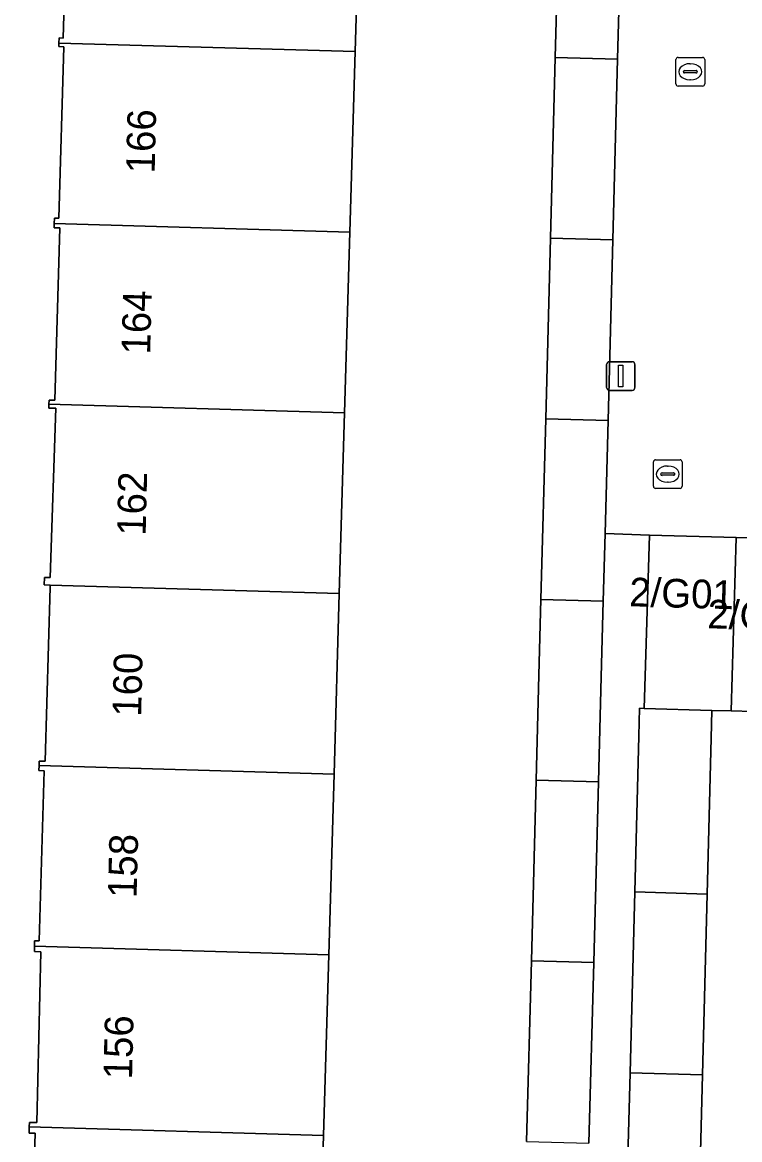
# Model space of a CAD drawing. Extents: x 162082 to 163401, y 388089 to 388636.
# Drawn here: x 162344.45 to 162369.45, y 388400.98 to 388439.93 of the extents above; entities that cross this region are included whole.
import ezdxf

# ---------------------------------------------------------------- set-up
doc = ezdxf.new("R2010")
doc.units = 0
for name, color, linetype in [('IMGEO_Erf', 7, 'Continuous'), ('IMGEO_Kolk', 7, 'Continuous'), ('IMGEO_Lichtmast', 7, 'Continuous'), ('IMGEO_Pand', 7, 'Continuous'), ('IMGEO_Pand_nummerreeks', 7, 'Continuous'), ('IMGEO_Rijbaan_lokaal_open', 7, 'Continuous'), ('IMGEO_Rioolput', 7, 'Continuous'), ('IMGEO_Voetpad_open', 7, 'Continuous')]:
    doc.layers.add(name, color=color, linetype=linetype)

msp = doc.modelspace()

# ---------------------------------------------------------------- linework, layer by layer
at = {"layer": 'IMGEO_Erf'}
for points in [[(162362.018, 388400.921), (162362.185, 388407.22), (162362.352, 388413.517), (162362.449, 388417.176), (162362.519, 388419.817), (162362.686, 388426.113), (162362.853, 388432.41), (162363.02, 388438.709), (162363.187, 388445.007), (162363.338, 388450.704), (162365.51, 388450.646), (162365.74, 388455.41), (162360.743, 388455.573), (162356.57, 388455.71), (162356.269, 388446.627), (162356.228, 388445.209), (162356.044, 388438.912), (162355.86, 388432.614), (162355.677, 388426.317), (162355.493, 388420.021), (162355.31, 388413.722), (162355.126, 388407.425), (162354.942, 388401.127), (162354.759, 388394.83)], [(162344.724, 388395.302), (162344.896, 388401.204), (162344.683, 388401.21), (162344.689, 388401.425), (162344.694, 388401.584), (162344.952, 388401.578), (162345.087, 388407.535), (162344.864, 388407.54), (162344.869, 388407.723), (162344.875, 388407.916), (162345.036, 388407.912), (162345.209, 388413.842), (162345.026, 388413.848), (162345.031, 388414.021), (162345.035, 388414.18), (162345.236, 388414.174), (162345.413, 388420.245), (162345.415, 388420.314), (162345.205, 388420.32), (162345.213, 388420.583), (162345.421, 388420.577), (162345.608, 388426.477), (162345.369, 388426.484), (162345.373, 388426.617), (162345.378, 388426.763), (162345.573, 388426.758), (162345.749, 388432.767), (162345.553, 388432.773), (162345.557, 388432.914), (162345.563, 388433.104), (162345.715, 388433.1), (162345.89, 388439.082), (162345.717, 388439.088), (162345.721, 388439.212), (162345.726, 388439.387), (162345.868, 388439.383), (162346.041, 388445.333)]]:
    msp.add_lwpolyline(points, dxfattribs=at)
msp.add_lwpolyline([(162376.236, 388396.697), (162376.423, 388402.994), (162376.61, 388409.292), (162376.8, 388415.702), (162375.2, 388415.749), (162372.174, 388415.837), (162369.148, 388415.926), (162368.481, 388415.945), (162368.456, 388414.976), (162368.314, 388409.541), (162368.148, 388403.242), (162367.983, 388396.945), (162367.818, 388390.647), (162367.652, 388384.348), (162367.487, 388378.051), (162367.322, 388371.753), (162367.158, 388365.51), (162364.636, 388365.576), (162364.63, 388365.331), (162375.298, 388365.051), (162375.489, 388371.508), (162375.676, 388377.805), (162375.863, 388384.102), (162376.05, 388390.4)], close=True, dxfattribs=at)
at = {"layer": 'IMGEO_Kolk'}
for p, q in [((162367.225, 388437.784), (162367.225, 388438.636)), ((162367.3, 388438.71), (162368.152, 388438.71)), ((162367.713, 388438.49), (162367.738, 388438.49)), ((162368.226, 388438.636), (162368.226, 388437.784)), ((162367.484, 388438.204), (162367.484, 388438.216)), ((162367.922, 388438.167), (162367.524, 388438.167)), ((162367.527, 388438.253), (162367.925, 388438.253)), ((162367.968, 388438.216), (162367.968, 388438.204)), ((162368.152, 388437.71), (162367.3, 388437.71)), ((162367.736, 388437.93), (162367.711, 388437.93))]:
    msp.add_line(p, q, dxfattribs=at)
for points in [[(162367.225, 388437.784), (162367.225, 388438.636)], [(162367.3, 388438.71), (162368.152, 388438.71)], [(162368.226, 388438.636), (162368.226, 388437.784)], [(162368.152, 388437.71), (162367.3, 388437.71)]]:
    msp.add_lwpolyline(points, dxfattribs=at)
for centre, radius, start, end in [((162367.302, 388438.634), 0.0765, 91.552, 178.448), ((162367.302, 388438.634), 0.0765, 91.552, 178.448), ((162368.15, 388438.634), 0.0765, 1.552, 88.448), ((162368.15, 388438.634), 0.0765, 1.552, 88.448), ((162367.524, 388438.213), 0.0403, 85.8775, 175.7526), ((162367.521, 388438.203), 0.0366, 178.938, 274.7102), ((162367.925, 388438.21), 0.043, 264.8664, 352.4533), ((162367.929, 388438.215), 0.0386, 1.7309, 96.639), ((162367.302, 388437.786), 0.0765, 181.552, 268.448), ((162367.302, 388437.786), 0.0765, 181.552, 268.448), ((162368.15, 388437.786), 0.0765, 271.552, 358.448), ((162368.15, 388437.786), 0.0765, 271.552, 358.448)]:
    msp.add_arc(centre, radius, start, end, dxfattribs=at)
for centre, major_axis, ratio, start_param, end_param in [((162367.712, 388438.21), (-0.387, 0.002), 0.722429, 4.712389, 7.853982), ((162367.737, 388438.21), (-0.39, 0.002), 0.717154, 1.570796, 4.712389)]:
    msp.add_ellipse(centre, major_axis=major_axis, ratio=ratio, start_param=start_param, end_param=end_param, dxfattribs=at)
at = {"layer": 'IMGEO_Lichtmast'}
for p, q in [((162364.805, 388427.203), (162364.805, 388428.003)), ((162364.805, 388428.003), (162364.805, 388427.203)), ((162364.905, 388428.103), (162365.695, 388428.103)), ((162365.695, 388428.103), (162364.905, 388428.103)), ((162365.795, 388428.003), (162365.795, 388427.203)), ((162365.795, 388427.203), (162365.795, 388428.003)), ((162365.695, 388427.103), (162364.905, 388427.103)), ((162364.905, 388427.103), (162365.695, 388427.103))]:
    msp.add_line(p, q, dxfattribs=at)
msp.add_lwpolyline([(162365.225, 388427.978), (162365.375, 388427.978), (162365.375, 388427.228), (162365.225, 388427.228), (162365.225, 388427.978)], dxfattribs=at)
for centre, start, end in [((162364.905, 388428.003), 90, 180), ((162364.905, 388428.003), 90, 180), ((162365.695, 388428.003), 0, 90), ((162365.695, 388428.003), 360, 90), ((162364.905, 388427.203), 180, 270), ((162364.905, 388427.203), 180, 270), ((162365.695, 388427.203), 270, 0), ((162365.695, 388427.203), 270, 0)]:
    msp.add_arc(centre, 0.1, start, end, dxfattribs=at)
at = {"layer": 'IMGEO_Pand'}
for points in [[(162345.897, 388445.509), (162345.892, 388445.338), (162346.041, 388445.333), (162345.868, 388439.383), (162345.726, 388439.387), (162345.721, 388439.212), (162356.044, 388438.912), (162356.228, 388445.209)], [(162363.02, 388438.709), (162365.192, 388438.646), (162365.359, 388444.944), (162363.187, 388445.007)], [(162356.044, 388438.912), (162345.721, 388439.212), (162345.717, 388439.088), (162345.89, 388439.082), (162345.715, 388433.1), (162345.563, 388433.104), (162345.557, 388432.914), (162355.86, 388432.614)], [(162363.02, 388438.709), (162362.853, 388432.41), (162365.025, 388432.347), (162365.192, 388438.646)], [(162355.677, 388426.317), (162355.86, 388432.614), (162345.557, 388432.914), (162345.553, 388432.773), (162345.749, 388432.767), (162345.573, 388426.758), (162345.378, 388426.763), (162345.373, 388426.617)], [(162364.858, 388426.05), (162365.025, 388432.347), (162362.853, 388432.41), (162362.686, 388426.113)], [(162355.677, 388426.317), (162345.373, 388426.617), (162345.369, 388426.484), (162345.608, 388426.477), (162345.421, 388420.577), (162345.213, 388420.583), (162345.205, 388420.32), (162345.415, 388420.314), (162355.493, 388420.021)], [(162364.858, 388426.05), (162362.686, 388426.113), (162362.519, 388419.817), (162364.692, 388419.754), (162364.754, 388422.116)], [(162369.325, 388421.97), (162366.299, 388422.059), (162366.122, 388416.014), (162368.481, 388415.945), (162369.148, 388415.926)], [(162372.174, 388415.837), (162372.351, 388421.882), (162369.325, 388421.97), (162369.148, 388415.926)], [(162355.493, 388420.021), (162345.415, 388420.314), (162345.413, 388420.245), (162345.236, 388414.174), (162345.035, 388414.18), (162345.031, 388414.021), (162355.31, 388413.722)], [(162362.352, 388413.517), (162364.525, 388413.454), (162364.622, 388417.118), (162364.692, 388419.754), (162362.519, 388419.817), (162362.449, 388417.176)], [(162368.456, 388414.976), (162368.481, 388415.945), (162366.122, 388416.014), (162365.959, 388416.019), (162365.934, 388415.042), (162365.792, 388409.617), (162368.314, 388409.541)], [(162345.031, 388414.021), (162345.026, 388413.848), (162345.209, 388413.842), (162345.036, 388407.912), (162344.875, 388407.916), (162344.869, 388407.723), (162355.126, 388407.425), (162355.31, 388413.722)], [(162364.358, 388407.157), (162364.525, 388413.454), (162362.352, 388413.517), (162362.185, 388407.22)], [(162365.792, 388409.617), (162365.626, 388403.317), (162368.148, 388403.242), (162368.314, 388409.541)], [(162344.689, 388401.425), (162354.942, 388401.127), (162355.126, 388407.425), (162344.869, 388407.723), (162344.864, 388407.54), (162345.087, 388407.535), (162344.952, 388401.578), (162344.694, 388401.584)], [(162364.358, 388407.157), (162362.185, 388407.22), (162362.018, 388400.921), (162364.19, 388400.858)], [(162367.983, 388396.945), (162368.148, 388403.242), (162365.626, 388403.317), (162365.461, 388397.02)], [(162344.689, 388401.425), (162344.683, 388401.21), (162344.896, 388401.204), (162344.724, 388395.302), (162344.451, 388395.309), (162344.446, 388395.13), (162354.759, 388394.83), (162354.942, 388401.127)]]:
    msp.add_lwpolyline(points, close=True, dxfattribs=at)
at = {"layer": 'IMGEO_Rijbaan_lokaal_open'}
msp.add_lwpolyline([(162370.574, 388457.3), (162365.799, 388457.454), (162365.74, 388455.41), (162365.51, 388450.646), (162365.359, 388444.944), (162365.192, 388438.646), (162365.025, 388432.347), (162364.858, 388426.05), (162364.754, 388422.116), (162366.299, 388422.059), (162369.325, 388421.97), (162372.351, 388421.882)], dxfattribs=at)
at = {"layer": 'IMGEO_Rioolput'}
for p, q in [((162366.44, 388423.758), (162366.44, 388424.61)), ((162366.515, 388424.684), (162367.367, 388424.684)), ((162366.928, 388424.464), (162366.953, 388424.464)), ((162367.441, 388424.61), (162367.441, 388423.758)), ((162366.699, 388424.178), (162366.699, 388424.19)), ((162367.137, 388424.141), (162366.739, 388424.141)), ((162366.742, 388424.227), (162367.14, 388424.227)), ((162367.183, 388424.19), (162367.183, 388424.178)), ((162367.367, 388423.684), (162366.515, 388423.684)), ((162366.951, 388423.904), (162366.926, 388423.904))]:
    msp.add_line(p, q, dxfattribs=at)
for points in [[(162366.44, 388423.758), (162366.44, 388424.61)], [(162366.515, 388424.684), (162367.367, 388424.684)], [(162367.441, 388424.61), (162367.441, 388423.758)], [(162367.367, 388423.684), (162366.515, 388423.684)]]:
    msp.add_lwpolyline(points, dxfattribs=at)
for centre, radius, start, end in [((162366.517, 388424.608), 0.0765, 91.552, 178.448), ((162366.517, 388424.608), 0.0765, 91.552, 178.448), ((162367.365, 388424.608), 0.0765, 1.552, 88.448), ((162367.365, 388424.608), 0.0765, 1.552, 88.448), ((162366.739, 388424.187), 0.0403, 85.8775, 175.7526), ((162366.736, 388424.177), 0.0366, 178.938, 274.7102), ((162367.14, 388424.184), 0.043, 264.8664, 352.4533), ((162367.144, 388424.189), 0.0386, 1.7309, 96.639), ((162366.517, 388423.76), 0.0765, 181.552, 268.448), ((162366.517, 388423.76), 0.0765, 181.552, 268.448), ((162367.365, 388423.76), 0.0765, 271.552, 358.448), ((162367.365, 388423.76), 0.0765, 271.552, 358.448)]:
    msp.add_arc(centre, radius, start, end, dxfattribs=at)
for centre, major_axis, ratio, start_param, end_param in [((162366.927, 388424.184), (-0.387, 0.002), 0.722429, 4.712389, 7.853982), ((162366.952, 388424.184), (-0.39, 0.002), 0.717154, 1.570796, 4.712389)]:
    msp.add_ellipse(centre, major_axis=major_axis, ratio=ratio, start_param=start_param, end_param=end_param, dxfattribs=at)
at = {"layer": 'IMGEO_Voetpad_open'}
msp.add_lwpolyline([(162365.461, 388397.02), (162365.626, 388403.317), (162365.792, 388409.617), (162365.934, 388415.042), (162365.959, 388416.019), (162366.122, 388416.014), (162366.299, 388422.059), (162364.754, 388422.116), (162364.692, 388419.754), (162364.622, 388417.118), (162364.525, 388413.454), (162364.358, 388407.157), (162364.19, 388400.858)], dxfattribs=at)

# ---------------------------------------------------------------- texts
at = {"layer": 'IMGEO_Pand_nummerreeks'}
for s, rotation, p in [('166', 88.5712, (162349.056, 388434.661)), ('164', 88.5712, (162348.899, 388428.344)), ('162', 88.5735, (162348.742, 388422.026)), ('2/G01', 358.3155, (162365.586, 388419.579)), ('2/G02', 358.2101, (162368.311, 388418.812)), ('160', 88.5735, (162348.584, 388415.715)), ('158', 88.5712, (162348.426, 388409.397)), ('156', 88.5712, (162348.268, 388403.076))]:
    msp.add_text(s, height=1, rotation=rotation, dxfattribs=at).set_placement(p)

doc.saveas('drawing.dxf')
